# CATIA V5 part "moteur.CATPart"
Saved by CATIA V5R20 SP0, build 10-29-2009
Part number: Nema 17
Revision: HERHANGÝ
Definition: BÝLÝNMEYEN
Nomenclature: Nema 17
Source: Unknown
Bounding box of the stored display mesh (mm): x -50 to 50, y -50 to 50, z -33.5 to 32.5
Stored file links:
  C:\Users\halimelbaba\Documents\cmv\final\moteur.CATPart
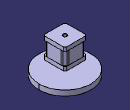
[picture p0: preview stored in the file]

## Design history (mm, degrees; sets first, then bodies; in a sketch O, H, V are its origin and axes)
Set1
  Plane1: type Offset, RefPlane face of Solid1, Offset 0, reversed
  Sketch1 on Plane1, origin (-20.9997, 0, 0), H (0, 1, 0), V (0, 0, 1)
    point P1 (13.757, 0)
    line L1 (13.757, 0) -> (-15.8783, 0)
    line L2 (-15.8783, 0) -> (-15.8783, 25)
    line L3 (-15.8783, 25) -> (13.757, 25)
    line L4 (13.757, 25) -> (13.757, 0)
    reference projected line E1 (13.757, 25) -> (13.757, 0) from edge [face of Solid1 | face of Solid1]
    reference projected line E2 (-13.757, 25) -> (13.757, 25) from edge [face of Solid1 | face of Solid1]
    reference projected line E3 (-15.8783, 25) -> (-15.8783, 0) from edge [face of Solid1 | face of Solid1]
    coincidence: P1 H, L4 E1, L3 E2, L2 E3
    horizontal: L1 H, L3 H
    vertical: L2 V, L4 V
Body1 "Yükseklik-Ekstrüzyon8" (main body)
  Solid1: solid without history
  Pad1: profile Sketch1, direction (1, 0, 0), length 2
  Pad2: profile Sketch1, direction (-1, 0, 0), length 0.1
  Plane2: type Offset, RefPlane face of Solid1, Offset 0, reversed
  Sketch2 on Plane2, origin (0, 0, -33.5), H (1, 0, 0), V (0, 1, 0)
    circle A1 centre (0, 0) radius 50
    radius A1 = 50
  Pad3: profile Sketch2, direction (0, 0, 1), length 10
